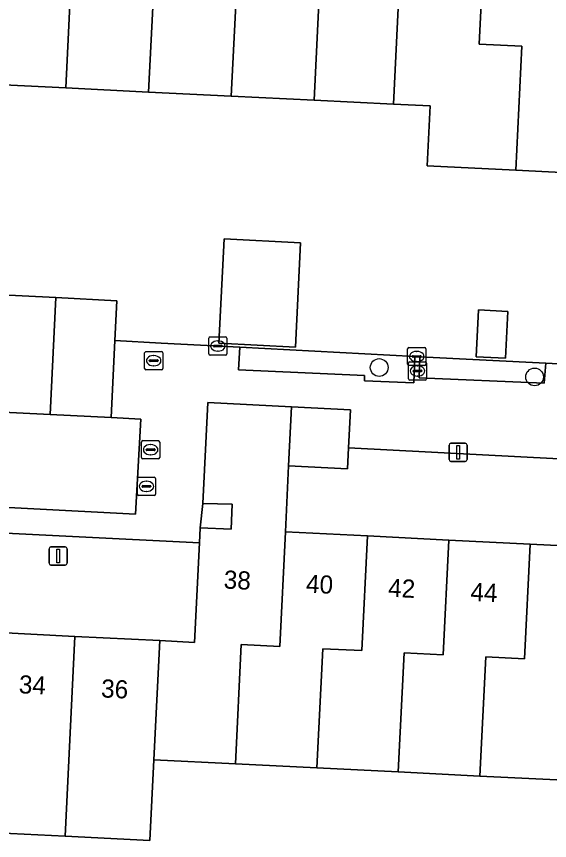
# Model space of a CAD drawing. Extents: x 162989 to 165008, y 383432 to 384338.
# Drawn here: x 164414.28 to 164443.65, y 383594.77 to 383640.13 of the extents above; entities that cross this region are included whole.
import ezdxf

# ---------------------------------------------------------------- set-up
doc = ezdxf.new("R2010")
doc.units = 0
for name, color, linetype in [('IMGEO_Boom', 7, 'Continuous'), ('IMGEO_Erf', 7, 'Continuous'), ('IMGEO_Groenvoorziening', 7, 'Continuous'), ('IMGEO_Kolk', 7, 'Continuous'), ('IMGEO_Lichtmast', 7, 'Continuous'), ('IMGEO_Pand', 7, 'Continuous'), ('IMGEO_Pand_nummerreeks', 7, 'Continuous'), ('IMGEO_Rijbaan_lokaal_open', 7, 'Continuous'), ('IMGEO_Rioolput', 7, 'Continuous'), ('IMGEO_Voetpad_open', 7, 'Continuous')]:
    doc.layers.add(name, color=color, linetype=linetype)

msp = doc.modelspace()

# ---------------------------------------------------------------- linework, layer by layer
at = {"layer": 'IMGEO_Boom'}
for centre in [(164434.265, 383620.808), (164442.83, 383620.289)]:
    msp.add_circle(centre, 0.489, dxfattribs=at)
at = {"layer": 'IMGEO_Erf'}
for points in [[(164413.084, 383624.821), (164416.448, 383624.655), (164419.808, 383624.489), (164419.699, 383622.289), (164422.254, 383622.155), (164426.592, 383621.927), (164436.231, 383621.42), (164436.501, 383621.406), (164443.456, 383621.04), (164445.87, 383620.914), (164446.254, 383627.641), (164446.273, 383627.973), (164446.293, 383628.307), (164446.472, 383631.437), (164441.793, 383631.668), (164436.903, 383631.91), (164437.066, 383635.209), (164435.056, 383635.308), (164430.674, 383635.525), (164426.113, 383635.75), (164421.553, 383635.975), (164416.992, 383636.2), (164412.431, 383636.425)], [(164444.176, 383615.776), (164432.572, 383616.394), (164432.514, 383615.227), (164429.274, 383615.388), (164429.095, 383611.759), (164433.616, 383611.534), (164438.103, 383611.31), (164442.593, 383611.087), (164447.059, 383610.864)], [(164444.444, 383598.088), (164439.809, 383598.319), (164435.32, 383598.542), (164430.832, 383598.766), (164426.343, 383598.989), (164421.855, 383599.213), (164421.634, 383594.769), (164416.958, 383595.002), (164412.43, 383595.227)]]:
    msp.add_lwpolyline(points, dxfattribs=at)
for points in [[(164425.721, 383627.888), (164429.935, 383627.678), (164429.648, 383621.932), (164425.434, 383622.142)], [(164441.351, 383623.894), (164441.216, 383621.319), (164439.605, 383621.404), (164439.741, 383623.979)], [(164424.362, 383611.166), (164395.258, 383612.608), (164395.322, 383613.893), (164395.054, 383613.906), (164394.717, 383607.141), (164399.393, 383606.908), (164403.92, 383606.683), (164408.448, 383606.457), (164412.975, 383606.232), (164417.503, 383606.006), (164422.18, 383605.773), (164424.088, 383605.678)], [(164424.403, 383611.992), (164426.101, 383611.908), (164426.17, 383613.277), (164424.549, 383613.316)]]:
    msp.add_lwpolyline(points, close=True, dxfattribs=at)
at = {"layer": 'IMGEO_Groenvoorziening'}
for points in [[(164436.231, 383621.42), (164426.592, 383621.927), (164426.514, 383620.674), (164433.452, 383620.374), (164433.451, 383620.083), (164436.183, 383619.974)], [(164443.456, 383621.04), (164436.501, 383621.406), (164436.464, 383620.243), (164443.353, 383619.956)]]:
    msp.add_lwpolyline(points, close=True, dxfattribs=at)
at = {"layer": 'IMGEO_Kolk'}
for p, q in [((164424.877, 383621.565), (164424.877, 383622.417)), ((164424.952, 383622.491), (164425.804, 383622.491)), ((164425.878, 383622.417), (164425.878, 383621.565)), ((164425.136, 383621.985), (164425.136, 383621.997)), ((164425.574, 383621.948), (164425.176, 383621.948)), ((164425.179, 383622.034), (164425.577, 383622.034)), ((164425.365, 383622.271), (164425.39, 383622.271)), ((164425.62, 383621.997), (164425.62, 383621.985)), ((164425.804, 383621.491), (164424.952, 383621.491)), ((164425.388, 383621.711), (164425.363, 383621.711)), ((164435.832, 383620.99), (164435.832, 383621.842)), ((164435.907, 383621.916), (164436.759, 383621.916)), ((164436.32, 383621.696), (164436.345, 383621.696)), ((164436.833, 383621.842), (164436.833, 383620.99)), ((164435.875, 383620.194), (164435.875, 383621.046)), ((164435.95, 383621.12), (164436.802, 383621.12)), ((164436.091, 383621.41), (164436.091, 383621.422)), ((164436.529, 383621.373), (164436.131, 383621.373)), ((164436.134, 383621.459), (164436.532, 383621.459)), ((164436.343, 383621.136), (164436.318, 383621.136)), ((164436.575, 383621.422), (164436.575, 383621.41)), ((164436.876, 383621.046), (164436.876, 383620.194)), ((164436.759, 383620.916), (164435.907, 383620.916)), ((164436.134, 383620.614), (164436.134, 383620.626)), ((164436.572, 383620.577), (164436.174, 383620.577)), ((164436.177, 383620.663), (164436.575, 383620.663)), ((164436.363, 383620.9), (164436.388, 383620.9)), ((164436.618, 383620.626), (164436.618, 383620.614)), ((164436.802, 383620.12), (164435.95, 383620.12)), ((164436.386, 383620.34), (164436.361, 383620.34)), ((164420.939, 383613.84), (164420.939, 383614.692)), ((164421.014, 383614.766), (164421.866, 383614.766)), ((164421.94, 383614.692), (164421.94, 383613.84)), ((164421.198, 383614.26), (164421.198, 383614.272)), ((164421.636, 383614.223), (164421.238, 383614.223)), ((164421.241, 383614.309), (164421.639, 383614.309)), ((164421.427, 383614.546), (164421.452, 383614.546)), ((164421.682, 383614.272), (164421.682, 383614.26)), ((164421.866, 383613.766), (164421.014, 383613.766)), ((164421.45, 383613.986), (164421.425, 383613.986))]:
    msp.add_line(p, q, dxfattribs=at)
for points in [[(164424.877, 383621.565), (164424.877, 383622.417)], [(164424.952, 383622.491), (164425.804, 383622.491)], [(164425.878, 383622.417), (164425.878, 383621.565)], [(164425.804, 383621.491), (164424.952, 383621.491)], [(164435.832, 383620.99), (164435.832, 383621.842)], [(164435.907, 383621.916), (164436.759, 383621.916)], [(164436.833, 383621.842), (164436.833, 383620.99)], [(164435.875, 383620.194), (164435.875, 383621.046)], [(164435.95, 383621.12), (164436.802, 383621.12)], [(164436.876, 383621.046), (164436.876, 383620.194)], [(164436.759, 383620.916), (164435.907, 383620.916)], [(164436.802, 383620.12), (164435.95, 383620.12)], [(164420.939, 383613.84), (164420.939, 383614.692)], [(164421.014, 383614.766), (164421.866, 383614.766)], [(164421.94, 383614.692), (164421.94, 383613.84)], [(164421.866, 383613.766), (164421.014, 383613.766)]]:
    msp.add_lwpolyline(points, dxfattribs=at)
for centre, radius, start, end in [((164424.954, 383622.415), 0.0765, 91.552, 178.448), ((164424.954, 383622.415), 0.0765, 91.552, 178.448), ((164425.802, 383622.415), 0.0765, 1.552, 88.448), ((164425.802, 383622.415), 0.0765, 1.552, 88.448), ((164425.176, 383621.994), 0.0403, 85.8775, 175.7526), ((164425.173, 383621.984), 0.0366, 178.938, 274.7102), ((164425.577, 383621.991), 0.043, 264.8664, 352.4533), ((164425.581, 383621.996), 0.0386, 1.7309, 96.639), ((164424.954, 383621.567), 0.0765, 181.552, 268.448), ((164424.954, 383621.567), 0.0765, 181.552, 268.448), ((164425.802, 383621.567), 0.0765, 271.552, 358.448), ((164425.802, 383621.567), 0.0765, 271.552, 358.448), ((164435.909, 383621.84), 0.0765, 91.552, 178.448), ((164435.909, 383621.84), 0.0765, 91.552, 178.448), ((164436.757, 383621.84), 0.0765, 1.552, 88.448), ((164436.757, 383621.84), 0.0765, 1.552, 88.448), ((164435.952, 383621.044), 0.0765, 91.552, 178.448), ((164435.952, 383621.044), 0.0765, 91.552, 178.448), ((164436.131, 383621.419), 0.0403, 85.8775, 175.7526), ((164436.128, 383621.409), 0.0366, 178.938, 274.7102), ((164436.532, 383621.416), 0.043, 264.8664, 352.4533), ((164436.536, 383621.421), 0.0386, 1.7309, 96.639), ((164436.8, 383621.044), 0.0765, 1.552, 88.448), ((164436.8, 383621.044), 0.0765, 1.552, 88.448), ((164435.909, 383620.992), 0.0765, 181.552, 268.448), ((164435.909, 383620.992), 0.0765, 181.552, 268.448), ((164436.174, 383620.623), 0.0403, 85.8775, 175.7526), ((164436.171, 383620.613), 0.0366, 178.938, 274.7102), ((164436.575, 383620.62), 0.043, 264.8664, 352.4533), ((164436.579, 383620.625), 0.0386, 1.7309, 96.639), ((164436.757, 383620.992), 0.0765, 271.552, 358.448), ((164436.757, 383620.992), 0.0765, 271.552, 358.448), ((164435.952, 383620.196), 0.0765, 181.552, 268.448), ((164435.952, 383620.196), 0.0765, 181.552, 268.448), ((164436.8, 383620.196), 0.0765, 271.552, 358.448), ((164436.8, 383620.196), 0.0765, 271.552, 358.448), ((164421.016, 383614.69), 0.0765, 91.552, 178.448), ((164421.016, 383614.69), 0.0765, 91.552, 178.448), ((164421.864, 383614.69), 0.0765, 1.552, 88.448), ((164421.864, 383614.69), 0.0765, 1.552, 88.448), ((164421.238, 383614.269), 0.0403, 85.8775, 175.7526), ((164421.235, 383614.259), 0.0366, 178.938, 274.7102), ((164421.639, 383614.266), 0.043, 264.8664, 352.4533), ((164421.643, 383614.271), 0.0386, 1.7309, 96.639), ((164421.016, 383613.842), 0.0765, 181.552, 268.448), ((164421.016, 383613.842), 0.0765, 181.552, 268.448), ((164421.864, 383613.842), 0.0765, 271.552, 358.448), ((164421.864, 383613.842), 0.0765, 271.552, 358.448)]:
    msp.add_arc(centre, radius, start, end, dxfattribs=at)
for centre, major_axis, ratio, start_param, end_param in [((164425.364, 383621.991), (-0.387, 0.002), 0.722429, 4.712389, 7.853982), ((164425.389, 383621.991), (-0.39, 0.002), 0.717154, 1.570796, 4.712389), ((164436.319, 383621.416), (-0.387, 0.002), 0.722429, 4.712389, 7.853982), ((164436.344, 383621.416), (-0.39, 0.002), 0.717154, 1.570796, 4.712389), ((164436.362, 383620.62), (-0.387, 0.002), 0.722429, 4.712389, 7.853982), ((164436.387, 383620.62), (-0.39, 0.002), 0.717154, 1.570796, 4.712389), ((164421.426, 383614.266), (-0.387, 0.002), 0.722429, 4.712389, 7.853982), ((164421.451, 383614.266), (-0.39, 0.002), 0.717154, 1.570796, 4.712389)]:
    msp.add_ellipse(centre, major_axis=major_axis, ratio=ratio, start_param=start_param, end_param=end_param, dxfattribs=at)
at = {"layer": 'IMGEO_Lichtmast'}
for p, q in [((164438.118, 383615.736), (164438.118, 383616.536)), ((164438.118, 383616.536), (164438.118, 383615.736)), ((164438.218, 383616.636), (164439.008, 383616.636)), ((164439.008, 383616.636), (164438.218, 383616.636)), ((164439.108, 383616.536), (164439.108, 383615.736)), ((164439.108, 383615.736), (164439.108, 383616.536)), ((164439.008, 383615.636), (164438.218, 383615.636)), ((164438.218, 383615.636), (164439.008, 383615.636)), ((164416.074, 383610.034), (164416.074, 383610.834)), ((164416.074, 383610.834), (164416.074, 383610.034)), ((164416.174, 383610.934), (164416.964, 383610.934)), ((164416.964, 383610.934), (164416.174, 383610.934)), ((164417.064, 383610.834), (164417.064, 383610.034)), ((164417.064, 383610.034), (164417.064, 383610.834)), ((164416.964, 383609.934), (164416.174, 383609.934)), ((164416.174, 383609.934), (164416.964, 383609.934))]:
    msp.add_line(p, q, dxfattribs=at)
for points in [[(164438.538, 383616.511), (164438.688, 383616.511), (164438.688, 383615.761), (164438.538, 383615.761), (164438.538, 383616.511)], [(164416.494, 383610.809), (164416.644, 383610.809), (164416.644, 383610.059), (164416.494, 383610.059), (164416.494, 383610.809)]]:
    msp.add_lwpolyline(points, dxfattribs=at)
for centre, start, end in [((164438.218, 383616.536), 90, 180), ((164438.218, 383616.536), 90, 180), ((164439.008, 383616.536), 0, 90), ((164439.008, 383616.536), 360, 90), ((164438.218, 383615.736), 180, 270), ((164438.218, 383615.736), 180, 270), ((164439.008, 383615.736), 270, 0), ((164439.008, 383615.736), 270, 0), ((164416.174, 383610.834), 90, 180), ((164416.174, 383610.834), 90, 180), ((164416.964, 383610.834), 0, 90), ((164416.964, 383610.834), 360, 90), ((164416.174, 383610.034), 180, 270), ((164416.174, 383610.034), 180, 270), ((164416.964, 383610.034), 270, 0), ((164416.964, 383610.034), 270, 0)]:
    msp.add_arc(centre, 0.1, start, end, dxfattribs=at)
at = {"layer": 'IMGEO_Pand'}
for points in [[(164412.431, 383636.425), (164416.992, 383636.2), (164417.316, 383642.694), (164414.969, 383642.811), (164415.294, 383649.311), (164410.733, 383649.536), (164410.408, 383643.036), (164412.755, 383642.919)], [(164419.659, 383649.095), (164415.294, 383649.311), (164414.969, 383642.811), (164417.316, 383642.694), (164416.992, 383636.2), (164421.553, 383635.975), (164421.877, 383642.469), (164419.53, 383642.586)], [(164426.113, 383635.75), (164426.437, 383642.244), (164424.09, 383642.361), (164424.414, 383648.86), (164419.659, 383649.095), (164419.53, 383642.586), (164421.877, 383642.469), (164421.553, 383635.975)], [(164426.113, 383635.75), (164430.674, 383635.525), (164430.998, 383642.02), (164428.651, 383642.137), (164428.975, 383648.635), (164424.414, 383648.86), (164424.09, 383642.361), (164426.437, 383642.244)], [(164435.54, 383645.151), (164433.53, 383645.25), (164433.686, 383648.402), (164428.975, 383648.635), (164428.651, 383642.137), (164430.998, 383642.02), (164430.674, 383635.525), (164435.056, 383635.308)], [(164435.54, 383645.151), (164435.056, 383635.308), (164437.066, 383635.209), (164436.903, 383631.91), (164441.793, 383631.668), (164442.128, 383638.503), (164439.781, 383638.618), (164440.09, 383644.926)], [(164440.09, 383644.926), (164439.781, 383638.618), (164442.128, 383638.503), (164441.793, 383631.668), (164446.472, 383631.437), (164446.81, 383638.275), (164444.455, 383638.392), (164444.613, 383641.587), (164444.766, 383644.695)], [(164425.434, 383622.142), (164429.648, 383621.932), (164429.935, 383627.678), (164425.721, 383627.888)], [(164416.128, 383618.216), (164416.448, 383624.655), (164413.084, 383624.821), (164412.862, 383620.332), (164412.766, 383618.382)], [(164416.128, 383618.216), (164419.49, 383618.05), (164419.699, 383622.289), (164419.808, 383624.489), (164416.448, 383624.655)], [(164441.351, 383623.894), (164439.741, 383623.979), (164439.605, 383621.404), (164441.216, 383621.319)], [(164422.18, 383605.773), (164421.855, 383599.213), (164426.343, 383598.989), (164426.668, 383605.552), (164428.783, 383605.447), (164429.095, 383611.759), (164429.274, 383615.388), (164429.435, 383618.649), (164424.826, 383618.879), (164424.549, 383613.316), (164426.17, 383613.277), (164426.101, 383611.908), (164424.403, 383611.992), (164424.362, 383611.166), (164424.088, 383605.678)], [(164429.274, 383615.388), (164432.514, 383615.227), (164432.572, 383616.394), (164432.676, 383618.487), (164429.435, 383618.649)], [(164426.343, 383598.989), (164430.832, 383598.766), (164431.157, 383605.328), (164433.304, 383605.222), (164433.616, 383611.534), (164429.095, 383611.759), (164428.783, 383605.447), (164426.668, 383605.552)], [(164438.103, 383611.31), (164433.616, 383611.534), (164433.304, 383605.222), (164431.157, 383605.328), (164430.832, 383598.766), (164435.32, 383598.542), (164435.645, 383605.104), (164437.792, 383604.998)], [(164438.103, 383611.31), (164437.792, 383604.998), (164435.645, 383605.104), (164435.32, 383598.542), (164439.809, 383598.319), (164440.134, 383604.881), (164442.281, 383604.775), (164442.593, 383611.087)], [(164447.059, 383610.864), (164442.593, 383611.087), (164442.281, 383604.775), (164440.134, 383604.881), (164439.809, 383598.319), (164444.444, 383598.088), (164444.602, 383601.261), (164446.577, 383601.163)], [(164412.43, 383595.227), (164416.958, 383595.002), (164417.503, 383606.006), (164412.975, 383606.232)], [(164422.18, 383605.773), (164417.503, 383606.006), (164416.958, 383595.002), (164421.634, 383594.769), (164421.855, 383599.213)]]:
    msp.add_lwpolyline(points, close=True, dxfattribs=at)
at = {"layer": 'IMGEO_Rijbaan_lokaal_open'}
msp.add_lwpolyline([(164405.01, 383625.534), (164405.012, 383625.572), (164403.719, 383625.636), (164400.452, 383625.806), (164395.832, 383626.048), (164391.39, 383626.279), (164388.178, 383626.447), (164382.262, 383626.794), (164382.991, 383640.31), (164377.994, 383640.557), (164376.972, 383621.957), (164397.683, 383620.748), (164397.37, 383613.969), (164420.832, 383612.735), (164421.124, 383617.97), (164419.49, 383618.05), (164416.128, 383618.216), (164412.766, 383618.382), (164412.862, 383620.332), (164411.887, 383620.383), (164408.032, 383620.586), (164404.773, 383620.747)], close=True, dxfattribs=at)
at = {"layer": 'IMGEO_Rioolput'}
for p, q in [((164421.339, 383620.757), (164421.339, 383621.609)), ((164421.414, 383621.683), (164422.266, 383621.683)), ((164422.34, 383621.609), (164422.34, 383620.757)), ((164421.598, 383621.177), (164421.598, 383621.189)), ((164422.036, 383621.14), (164421.638, 383621.14)), ((164421.641, 383621.226), (164422.039, 383621.226)), ((164421.827, 383621.463), (164421.852, 383621.463)), ((164422.082, 383621.189), (164422.082, 383621.177)), ((164422.266, 383620.683), (164421.414, 383620.683)), ((164421.85, 383620.903), (164421.825, 383620.903)), ((164421.171, 383615.856), (164421.171, 383616.708)), ((164421.246, 383616.782), (164422.098, 383616.782)), ((164421.659, 383616.562), (164421.684, 383616.562)), ((164422.172, 383616.708), (164422.172, 383615.856)), ((164421.43, 383616.276), (164421.43, 383616.288)), ((164421.868, 383616.239), (164421.47, 383616.239)), ((164421.473, 383616.325), (164421.871, 383616.325)), ((164421.914, 383616.288), (164421.914, 383616.276)), ((164422.098, 383615.782), (164421.246, 383615.782)), ((164421.682, 383616.002), (164421.657, 383616.002))]:
    msp.add_line(p, q, dxfattribs=at)
for points in [[(164421.339, 383620.757), (164421.339, 383621.609)], [(164421.414, 383621.683), (164422.266, 383621.683)], [(164422.34, 383621.609), (164422.34, 383620.757)], [(164422.266, 383620.683), (164421.414, 383620.683)], [(164421.171, 383615.856), (164421.171, 383616.708)], [(164421.246, 383616.782), (164422.098, 383616.782)], [(164422.172, 383616.708), (164422.172, 383615.856)], [(164422.098, 383615.782), (164421.246, 383615.782)]]:
    msp.add_lwpolyline(points, dxfattribs=at)
for centre, radius, start, end in [((164421.416, 383621.607), 0.0765, 91.552, 178.448), ((164421.416, 383621.607), 0.0765, 91.552, 178.448), ((164422.264, 383621.607), 0.0765, 1.552, 88.448), ((164422.264, 383621.607), 0.0765, 1.552, 88.448), ((164421.638, 383621.186), 0.0403, 85.8775, 175.7526), ((164421.635, 383621.176), 0.0366, 178.938, 274.7102), ((164422.039, 383621.183), 0.043, 264.8664, 352.4533), ((164422.043, 383621.188), 0.0386, 1.7309, 96.639), ((164421.416, 383620.759), 0.0765, 181.552, 268.448), ((164421.416, 383620.759), 0.0765, 181.552, 268.448), ((164422.264, 383620.759), 0.0765, 271.552, 358.448), ((164422.264, 383620.759), 0.0765, 271.552, 358.448), ((164421.248, 383616.706), 0.0765, 91.552, 178.448), ((164421.248, 383616.706), 0.0765, 91.552, 178.448), ((164422.096, 383616.706), 0.0765, 1.552, 88.448), ((164422.096, 383616.706), 0.0765, 1.552, 88.448), ((164421.47, 383616.285), 0.0403, 85.8775, 175.7526), ((164421.467, 383616.275), 0.0366, 178.938, 274.7102), ((164421.871, 383616.282), 0.043, 264.8664, 352.4533), ((164421.875, 383616.287), 0.0386, 1.7309, 96.639), ((164421.248, 383615.858), 0.0765, 181.552, 268.448), ((164421.248, 383615.858), 0.0765, 181.552, 268.448), ((164422.096, 383615.858), 0.0765, 271.552, 358.448), ((164422.096, 383615.858), 0.0765, 271.552, 358.448)]:
    msp.add_arc(centre, radius, start, end, dxfattribs=at)
for centre, major_axis, ratio, start_param, end_param in [((164421.826, 383621.183), (-0.387, 0.002), 0.722429, 4.712389, 7.853982), ((164421.851, 383621.183), (-0.39, 0.002), 0.717154, 1.570796, 4.712389), ((164421.658, 383616.282), (-0.387, 0.002), 0.722429, 4.712389, 7.853982), ((164421.683, 383616.282), (-0.39, 0.002), 0.717154, 1.570796, 4.712389)]:
    msp.add_ellipse(centre, major_axis=major_axis, ratio=ratio, start_param=start_param, end_param=end_param, dxfattribs=at)
at = {"layer": 'IMGEO_Voetpad_open'}
for points in [[(164456.703, 383629.199), (164456.673, 383627.538), (164456.422, 383620.433), (164447.758, 383620.816), (164445.87, 383620.914), (164443.456, 383621.04), (164443.353, 383619.956), (164436.464, 383620.243), (164436.501, 383621.406), (164436.231, 383621.42), (164436.183, 383619.974), (164433.451, 383620.083), (164433.452, 383620.374), (164426.514, 383620.674), (164426.592, 383621.927), (164422.254, 383622.155), (164419.699, 383622.289), (164419.49, 383618.05), (164421.124, 383617.97), (164420.832, 383612.735), (164397.37, 383613.969)], [(164395.258, 383612.608), (164424.362, 383611.166), (164424.403, 383611.992), (164424.549, 383613.316), (164424.826, 383618.879), (164429.435, 383618.649), (164432.676, 383618.487), (164432.572, 383616.394), (164444.176, 383615.776), (164444.281, 383617.896), (164447.469, 383617.737), (164447.457, 383617.504), (164458.712, 383616.925), (164458.849, 383619.676)]]:
    msp.add_lwpolyline(points, dxfattribs=at)

# ---------------------------------------------------------------- texts
at = {"layer": 'IMGEO_Pand_nummerreeks'}
for s, rotation, p in [('38', 357.1497, (164425.683, 383608.645)), ('40', 357.1497, (164430.215, 383608.419)), ('42', 357.1497, (164434.74, 383608.194)), ('44', 357.1497, (164439.274, 383607.968)), ('34', 357.1476, (164414.393, 383602.877)), ('36', 357.1476, (164418.925, 383602.652))]:
    msp.add_text(s, height=1, rotation=rotation, dxfattribs=at).set_placement(p)

doc.saveas('drawing.dxf')
